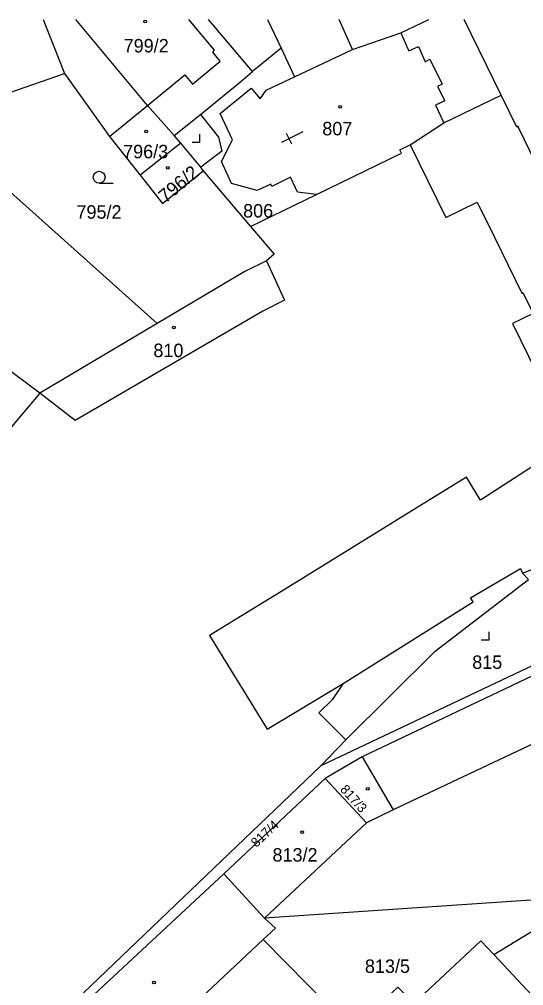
# Model space of a CAD drawing. Extents: x -496682 to -495776, y -1088797 to -1088018.
# Drawn here: x -496359.5 to -496295.8, y -1088141.5 to -1088019.5 of the extents above; entities that cross this region are included whole.
import ezdxf

# ---------------------------------------------------------------- set-up
doc = ezdxf.new("R2010")
doc.units = 0
for name, color, linetype in [('Hranice parcel', 7, 'Continuous'), ('Parcelní čísla', 7, 'Continuous'), ('Vnitřní kresba', 7, 'Continuous'), ('Značky budov', 7, 'Continuous'), ('Značky kultur', 7, 'Continuous')]:
    doc.layers.add(name, color=color, linetype=linetype)

msp = doc.modelspace()

# ---------------------------------------------------------------- linework, layer by layer
at = {"layer": 'Hranice parcel'}
for p, q in [((-496328.16, -1088019.49), (-496326.44, -1088023.13)), ((-496298.65, -1088029.08), (-496303.35, -1088019.49)), ((-496326.44, -1088023.13), (-496330.05, -1088026.09)), ((-496326.44, -1088023.13), (-496324.74, -1088026.75)), ((-496348.1, -1088034.29), (-496343.33, -1088030.37)), ((-496339.97, -1088034.14), (-496343.33, -1088030.37)), ((-496370.79, -1088032.22), (-496342.08, -1088057.91)), ((-496348.1, -1088034.29), (-496344.26, -1088039.18)), ((-496339.12, -1088035.12), (-496339.97, -1088034.14)), ((-496339.12, -1088035.12), (-496344.26, -1088039.18)), ((-496336.28, -1088038.61), (-496330.3, -1088045.65)), ((-496330.3, -1088045.65), (-496321.98, -1088041.61)), ((-496342.08, -1088057.91), (-496356.91, -1088066.71)), ((-496356.91, -1088066.71), (-496364.73, -1088060.87)), ((-496269.29, -1088090.31), (-496316.2, -1088112.62)), ((-496321.41, -1088113.75), (-496288.72, -1088098.27)), ((-496265.99, -1088097.42), (-496312.31, -1088119.35)), ((-496321.41, -1088113.75), (-496318.3, -1088110.48)), ((-496316.2, -1088112.62), (-496320.9, -1088115.37)), ((-496316.2, -1088112.62), (-496312.31, -1088119.35)), ((-496373.06, -1088163.12), (-496321.41, -1088113.75)), ((-496320.9, -1088115.37), (-496333.69, -1088127.43)), ((-496315.65, -1088120.99), (-496320.9, -1088115.37)), ((-496312.31, -1088119.35), (-496315.65, -1088120.99)), ((-496328.55, -1088133.03), (-496315.65, -1088120.99)), ((-496333.69, -1088127.43), (-496357.36, -1088149.42)), ((-496333.69, -1088127.43), (-496328.55, -1088133.03)), ((-496287.5, -1088130.23), (-496328.55, -1088133.03)), ((-496299.6, -1088137.62), (-496287.5, -1088130.23)), ((-496350.76, -1088156.43), (-496328.71, -1088135.71)), ((-496328.71, -1088135.71), (-496317.45, -1088147.13))]:
    msp.add_line(p, q, dxfattribs=at)
for points in [[(-496343.33, -1088030.37), (-496352.39, -1088019.49)], [(-496330.05, -1088026.09), (-496335.61, -1088019.49)], [(-496324.74, -1088026.75), (-496317.45, -1088023.28), (-496311.34, -1088021.2), (-496307.78, -1088019.49)], [(-496370.79, -1088032.22), (-496353.78, -1088026.33), (-496348.1, -1088034.29)], [(-496339.97, -1088034.14), (-496336.64, -1088031.5), (-496331.54, -1088027.32), (-496330.05, -1088026.09)], [(-496321.98, -1088041.61), (-496324.37, -1088041.31), (-496325.28, -1088039.42), (-496327.61, -1088040.59), (-496327.75, -1088040.32), (-496329.48, -1088041.1), (-496332.73, -1088040.23), (-496333.96, -1088037.46), (-496332.59, -1088034.7), (-496334.13, -1088031.37), (-496330.23, -1088028.2), (-496329.09, -1088029.54), (-496328.32, -1088028.45), (-496324.74, -1088026.75)], [(-496310.17, -1088035.32), (-496305.9, -1088032.56), (-496298.65, -1088029.08)], [(-496275.49, -1088077.48), (-496275.13, -1088077.26), (-496281.01, -1088065.15), (-496281.24, -1088065.26), (-496284.2, -1088059.06), (-496284.42, -1088058.56), (-496284.28, -1088058.49), (-496286.47, -1088053.98), (-496286.61, -1088054.04), (-496286.78, -1088053.72), (-496289.73, -1088047.63), (-496289.89, -1088047.33), (-496289.67, -1088047.22), (-496296.43, -1088033.23), (-496296.51, -1088033), (-496296.71, -1088033.1), (-496298.65, -1088029.08)], [(-496336.28, -1088038.61), (-496336.57, -1088038.17), (-496339.12, -1088035.12)], [(-496321.98, -1088041.61), (-496311.24, -1088036.41), (-496311.47, -1088035.95), (-496310.17, -1088035.32)], [(-496310.17, -1088035.32), (-496305.66, -1088044.52), (-496301.69, -1088042.58), (-496299.5, -1088047.02), (-496296.07, -1088054.07), (-496295.93, -1088054), (-496294.63, -1088056.63), (-496297.22, -1088057.91), (-496294.11, -1088064.26)], [(-496344.26, -1088039.18), (-496341.41, -1088042.74), (-496336.28, -1088038.61)], [(-496330.3, -1088045.65), (-496327.33, -1088049.15), (-496328.29, -1088049.97)], [(-496328.29, -1088049.97), (-496326.03, -1088054.97), (-496328.74, -1088056.34), (-496352.45, -1088070.14), (-496356.91, -1088066.71)], [(-496328.29, -1088049.97), (-496331.02, -1088051.35), (-496342.08, -1088057.91)], [(-496356.91, -1088066.71), (-496365.03, -1088076.3), (-496371.95, -1088081.22), (-496377.22, -1088075.77)], [(-496291.14, -1088073.66), (-496301.28, -1088080.22), (-496303.06, -1088077.33), (-496309.39, -1088081.23), (-496325.96, -1088091.45), (-496335.48, -1088097.3), (-496328.2, -1088109.13), (-496318.63, -1088103.36), (-496319.99, -1088105.46), (-496321.7, -1088107.07), (-496318.3, -1088110.48)], [(-496318.3, -1088110.48), (-496307.01, -1088099.28), (-496295.23, -1088090.25), (-496295.99, -1088089.43), (-496293.61, -1088088.52)], [(-496328.55, -1088133.03), (-496327.18, -1088134.28), (-496328.71, -1088135.71)], [(-496317.45, -1088147.13), (-496311.72, -1088141.73), (-496309.67, -1088143.77), (-496301.22, -1088135.9), (-496299.6, -1088137.62)], [(-496316.44, -1088148.1), (-496316.33, -1088148), (-496315.31, -1088149.08), (-496325.51, -1088158.67), (-496317.28, -1088167.48), (-496305.43, -1088156.36), (-496304.95, -1088156.9), (-496300.93, -1088153.13), (-496301.44, -1088152.61), (-496292.98, -1088144.67), (-496299.6, -1088137.62)]]:
    msp.add_lwpolyline(points, dxfattribs=at)
at = {"layer": 'Vnitřní kresba'}
for p, q in [((-496356.49, -1088019.49), (-496353.78, -1088026.33)), ((-496334.85, -1088023.38), (-496338.12, -1088019.49)), ((-496318.78, -1088020.28), (-496319.13, -1088019.49)), ((-496317.45, -1088023.28), (-496318.78, -1088020.28)), ((-496311.34, -1088021.2), (-496310.45, -1088023.2)), ((-496335.08, -1088023.62), (-496334.85, -1088023.38)), ((-496334.13, -1088024.78), (-496335.08, -1088023.62)), ((-496310.45, -1088023.2), (-496310.33, -1088023.47)), ((-496310.33, -1088023.47), (-496309.11, -1088022.93)), ((-496309.11, -1088022.93), (-496308.79, -1088023.6)), ((-496308.79, -1088023.6), (-496308.26, -1088024.86)), ((-496337.64, -1088027.69), (-496334.13, -1088024.78)), ((-496308.26, -1088024.86), (-496307.69, -1088024.52)), ((-496307.69, -1088024.52), (-496306.13, -1088027.69)), ((-496343.33, -1088030.37), (-496338.62, -1088026.5)), ((-496338.62, -1088026.5), (-496337.64, -1088027.69)), ((-496306.13, -1088027.69), (-496306.7, -1088027.99)), ((-496306.7, -1088027.99), (-496305.78, -1088029.78)), ((-496305.78, -1088029.78), (-496306.96, -1088030.34)), ((-496306.96, -1088030.34), (-496305.9, -1088032.56)), ((-496336.64, -1088031.5), (-496334.36, -1088034.39)), ((-496334.36, -1088034.39), (-496333.93, -1088036.13)), ((-496333.93, -1088036.13), (-496336.57, -1088038.17)), ((-496302.53, -1088092.55), (-496296.21, -1088088.86)), ((-496296.21, -1088088.86), (-496295.99, -1088089.43)), ((-496318.63, -1088103.36), (-496302.21, -1088093.07)), ((-496302.21, -1088093.07), (-496302.53, -1088092.55))]:
    msp.add_line(p, q, dxfattribs=at)
at = {"layer": 'Značky budov'}
for p, q in [((-496326.34, -1088035.02), (-496323.67, -1088033.66)), ((-496325.11, -1088035.24), (-496325.79, -1088033.9))]:
    msp.add_line(p, q, dxfattribs=at)
for centre in [(-496343.62, -1088019.75), (-496318.99, -1088030.54), (-496343.5, -1088033.65), (-496340.74, -1088038.23), (-496339.99, -1088058.42), (-496315.52, -1088116.68), (-496323.79, -1088122.15), (-496342.5, -1088141.14)]:
    msp.add_circle(centre, 0.175, dxfattribs=at)
at = {"layer": 'Značky kultur'}
for p, q in [((-496337.7, -1088034.99), (-496336.7, -1088034.99)), ((-496336.7, -1088034.99), (-496336.7, -1088033.99)), ((-496349.42, -1088040.18), (-496347.67, -1088040.18)), ((-496300.19, -1088097.85), (-496300.19, -1088096.85)), ((-496301.19, -1088097.85), (-496300.19, -1088097.85))]:
    msp.add_line(p, q, dxfattribs=at)
msp.add_circle((-496349.42, -1088039.43), 0.75, dxfattribs=at)

# ---------------------------------------------------------------- texts
at = {"layer": 'Parcelní čísla'}
for s, p in [('799/2', (-496346.33, -1088023.67)), ('807', (-496321.25, -1088034.14)), ('796/3', (-496346.4, -1088037.04)), ('795/2', (-496352.29, -1088044.67)), ('806', (-496331.25, -1088044.52)), ('810', (-496342.58, -1088062.15)), ('815', (-496302.32, -1088101.53)), ('813/2', (-496327.54, -1088125.87)), ('813/5', (-496315.87, -1088139.93))]:
    msp.add_text(s, height=1.7, dxfattribs=at).set_placement(p)
for s, height, rotation, p in [('796/2', 1.7, 40, (-496341.04, -1088042.76)), ('817/3', 1.2, 312, (-496319.08, -1088116.82)), ('817/4', 1.2, 43, (-496329.58, -1088124.15))]:
    msp.add_text(s, height=height, rotation=rotation, dxfattribs=at).set_placement(p)

doc.saveas('drawing.dxf')
